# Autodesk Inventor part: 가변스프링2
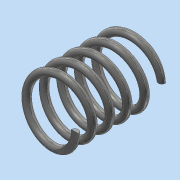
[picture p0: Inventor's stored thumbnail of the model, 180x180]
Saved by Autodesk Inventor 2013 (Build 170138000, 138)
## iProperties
Created: 2018-10
Part Number: 가변스프링2
Material: 스테인리스강
Document SubType Name: Modeling
Designer: Administrator
Density: 1 g/cm^3
Mass: 0.775508 g
Surface Area: 15.7576 cm^2
Volume: 0.775508 cm^3
Author: Administrator
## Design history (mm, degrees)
sketch "스케치1"
  geometry: L1 (0, 0)-(0, -24.527); L2 (8, 0)-(0, 0); L3 (0, -24.527)-(8, -24.527); C1 r 1 at (8, 0)
  constraints: 6 end point, 1 centre point, 1 horizontal alignment, 1 parallel, 1 perpendicular, 1 vertical
  dimensions: "d0" = 24.52707 distance of L1.start L1.end (derived); "d1" = 2 diameter of C1; "d2" = 16 diameter of L2.start L1; "d3" = 8 distance of L1.end L3.end
feature "코일1" sketch "스케치1" pitch "d4" = 10; turns "d6" = 5; dims "d5" = 24.52707 (= d0), "d7" = 0, angle "d8" = 90 deg, angle "d9" = 90 deg, "d10" = 0, "d11" = 0
sketch "스케치2"
  geometry: L1 (-24.527, 10)-(0, 10); L2 (0, 10)-(0, -10); L3 (0, -10)-(-24.527, -10); L4 (-24.527, -10)-(-24.527, 10); 2 further points
  constraints: 8 end point, 2 parallel, 1 coincident, 1 horizontal, 1 midpoint, 1 perpendicular
  dimensions: "d12" = 24.52707 distance of L2.end L3.end (derived); "d14" = 20 distance of L1.end L2.end
extrude "돌출1" sketch "스케치2" stored distance "d15" = 0; taper "d16" = 0 deg
node "솔리드1"
